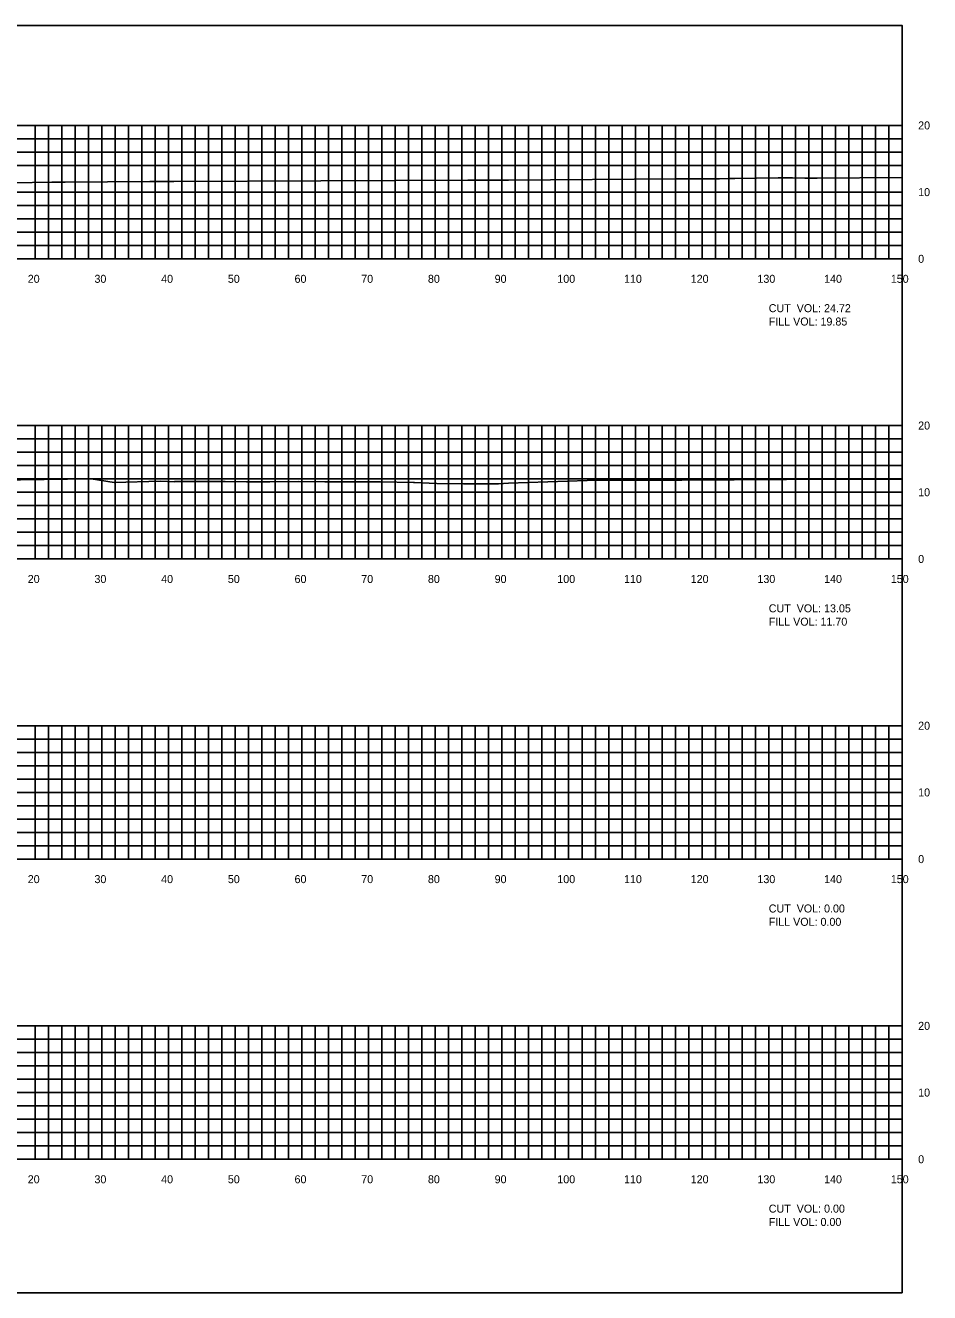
# Model space of a CAD drawing. Extents: x 1800768 to 1802445, y 250079 to 250269.
# Drawn here: x 1802309.5 to 1802445.1, y 250079.4 to 250269.4 of the extents above; entities that cross this region are included whole.
import ezdxf

# ---------------------------------------------------------------- set-up
doc = ezdxf.new("R2010")
doc.units = 0
for name, color, linetype in [('10', 7, 'Continuous'), ('31', 7, 'Continuous'), ('60', 7, 'Continuous'), ('ANNO-TXT', 7, 'Continuous'), ('Level 62', 7, 'Continuous'), ('M-ROADS', 7, 'Continuous')]:
    doc.layers.add(name, color=color, linetype=linetype)

msp = doc.modelspace()

# ---------------------------------------------------------------- linework, layer by layer
msp.add_lwpolyline([(1802141, 250079.43), (1802441, 250079.43), (1802441, 250269.43), (1802141, 250269.43)], close=True)
at = {"layer": '60'}
for p, q in [((1802441, 250234.43), (1802441, 250254.43)), ((1802441.06, 250254.43), (1802441, 250254.43)), ((1802441.06, 250244.43), (1802441, 250244.43)), ((1802141, 250234.43), (1802441, 250234.43)), ((1802311, 250234.37), (1802311, 250234.43)), ((1802321, 250234.37), (1802321, 250234.43)), ((1802331, 250234.37), (1802331, 250234.43)), ((1802341, 250234.37), (1802341, 250234.43)), ((1802351, 250234.37), (1802351, 250234.43)), ((1802361, 250234.37), (1802361, 250234.43)), ((1802371, 250234.37), (1802371, 250234.43)), ((1802381, 250234.37), (1802381, 250234.43)), ((1802391, 250234.37), (1802391, 250234.43)), ((1802401, 250234.37), (1802401, 250234.43)), ((1802411, 250234.37), (1802411, 250234.43)), ((1802421, 250234.37), (1802421, 250234.43)), ((1802431, 250234.37), (1802431, 250234.43)), ((1802441, 250234.37), (1802441, 250234.43)), ((1802441.06, 250234.43), (1802441, 250234.43)), ((1802441, 250189.43), (1802441, 250209.43)), ((1802441.06, 250209.43), (1802441, 250209.43)), ((1802441.06, 250199.43), (1802441, 250199.43)), ((1802141, 250189.43), (1802441, 250189.43)), ((1802311, 250189.37), (1802311, 250189.43)), ((1802321, 250189.37), (1802321, 250189.43)), ((1802331, 250189.37), (1802331, 250189.43)), ((1802341, 250189.37), (1802341, 250189.43)), ((1802351, 250189.37), (1802351, 250189.43)), ((1802361, 250189.37), (1802361, 250189.43)), ((1802371, 250189.37), (1802371, 250189.43)), ((1802381, 250189.37), (1802381, 250189.43)), ((1802391, 250189.37), (1802391, 250189.43)), ((1802401, 250189.37), (1802401, 250189.43)), ((1802411, 250189.37), (1802411, 250189.43)), ((1802421, 250189.37), (1802421, 250189.43)), ((1802431, 250189.37), (1802431, 250189.43)), ((1802441, 250189.37), (1802441, 250189.43)), ((1802441.06, 250189.43), (1802441, 250189.43)), ((1802441, 250144.43), (1802441, 250164.43)), ((1802441.06, 250164.43), (1802441, 250164.43)), ((1802441.06, 250154.43), (1802441, 250154.43)), ((1802141, 250144.43), (1802441, 250144.43)), ((1802311, 250144.37), (1802311, 250144.43)), ((1802321, 250144.37), (1802321, 250144.43)), ((1802331, 250144.37), (1802331, 250144.43)), ((1802341, 250144.37), (1802341, 250144.43)), ((1802351, 250144.37), (1802351, 250144.43)), ((1802361, 250144.37), (1802361, 250144.43)), ((1802371, 250144.37), (1802371, 250144.43)), ((1802381, 250144.37), (1802381, 250144.43)), ((1802391, 250144.37), (1802391, 250144.43)), ((1802401, 250144.37), (1802401, 250144.43)), ((1802411, 250144.37), (1802411, 250144.43)), ((1802421, 250144.37), (1802421, 250144.43)), ((1802431, 250144.37), (1802431, 250144.43)), ((1802441, 250144.37), (1802441, 250144.43)), ((1802441.06, 250144.43), (1802441, 250144.43)), ((1802441, 250099.43), (1802441, 250119.43)), ((1802441.06, 250119.43), (1802441, 250119.43)), ((1802441.06, 250109.43), (1802441, 250109.43)), ((1802141, 250099.43), (1802441, 250099.43)), ((1802311, 250099.37), (1802311, 250099.43)), ((1802321, 250099.37), (1802321, 250099.43)), ((1802331, 250099.37), (1802331, 250099.43)), ((1802341, 250099.37), (1802341, 250099.43)), ((1802351, 250099.37), (1802351, 250099.43)), ((1802361, 250099.37), (1802361, 250099.43)), ((1802371, 250099.37), (1802371, 250099.43)), ((1802381, 250099.37), (1802381, 250099.43)), ((1802391, 250099.37), (1802391, 250099.43)), ((1802401, 250099.37), (1802401, 250099.43)), ((1802411, 250099.37), (1802411, 250099.43)), ((1802421, 250099.37), (1802421, 250099.43)), ((1802431, 250099.37), (1802431, 250099.43)), ((1802441, 250099.37), (1802441, 250099.43)), ((1802441.06, 250099.43), (1802441, 250099.43))]:
    msp.add_line(p, q, dxfattribs=at)
at = {"layer": 'Level 62'}
for p, q in [((1802141, 250254.43), (1802441, 250254.43)), ((1802311, 250234.43), (1802311, 250254.43)), ((1802313, 250234.43), (1802313, 250254.43)), ((1802315, 250234.43), (1802315, 250254.43)), ((1802317, 250234.43), (1802317, 250254.43)), ((1802319, 250234.43), (1802319, 250254.43)), ((1802321, 250234.43), (1802321, 250254.43)), ((1802323, 250234.43), (1802323, 250254.43)), ((1802325, 250234.43), (1802325, 250254.43)), ((1802327, 250234.43), (1802327, 250254.43)), ((1802329, 250234.43), (1802329, 250254.43)), ((1802331, 250234.43), (1802331, 250254.43)), ((1802333, 250234.43), (1802333, 250254.43)), ((1802335, 250234.43), (1802335, 250254.43)), ((1802337, 250234.43), (1802337, 250254.43)), ((1802339, 250234.43), (1802339, 250254.43)), ((1802341, 250234.43), (1802341, 250254.43)), ((1802343, 250234.43), (1802343, 250254.43)), ((1802345, 250234.43), (1802345, 250254.43)), ((1802347, 250234.43), (1802347, 250254.43)), ((1802349, 250234.43), (1802349, 250254.43)), ((1802351, 250234.43), (1802351, 250254.43)), ((1802353, 250234.43), (1802353, 250254.43)), ((1802355, 250234.43), (1802355, 250254.43)), ((1802357, 250234.43), (1802357, 250254.43)), ((1802359, 250234.43), (1802359, 250254.43)), ((1802361, 250234.43), (1802361, 250254.43)), ((1802363, 250234.43), (1802363, 250254.43)), ((1802365, 250234.43), (1802365, 250254.43)), ((1802367, 250234.43), (1802367, 250254.43)), ((1802369, 250234.43), (1802369, 250254.43)), ((1802371, 250234.43), (1802371, 250254.43)), ((1802373, 250234.43), (1802373, 250254.43)), ((1802375, 250234.43), (1802375, 250254.43)), ((1802377, 250234.43), (1802377, 250254.43)), ((1802379, 250234.43), (1802379, 250254.43)), ((1802381, 250234.43), (1802381, 250254.43)), ((1802383, 250234.43), (1802383, 250254.43)), ((1802385, 250234.43), (1802385, 250254.43)), ((1802387, 250234.43), (1802387, 250254.43)), ((1802389, 250234.43), (1802389, 250254.43)), ((1802391, 250234.43), (1802391, 250254.43)), ((1802393, 250234.43), (1802393, 250254.43)), ((1802395, 250234.43), (1802395, 250254.43)), ((1802397, 250234.43), (1802397, 250254.43)), ((1802399, 250234.43), (1802399, 250254.43)), ((1802401, 250234.43), (1802401, 250254.43)), ((1802403, 250234.43), (1802403, 250254.43)), ((1802405, 250234.43), (1802405, 250254.43)), ((1802407, 250234.43), (1802407, 250254.43)), ((1802409, 250234.43), (1802409, 250254.43)), ((1802411, 250234.43), (1802411, 250254.43)), ((1802413, 250234.43), (1802413, 250254.43)), ((1802415, 250234.43), (1802415, 250254.43)), ((1802417, 250234.43), (1802417, 250254.43)), ((1802419, 250234.43), (1802419, 250254.43)), ((1802421, 250234.43), (1802421, 250254.43)), ((1802423, 250234.43), (1802423, 250254.43)), ((1802425, 250234.43), (1802425, 250254.43)), ((1802427, 250234.43), (1802427, 250254.43)), ((1802429, 250234.43), (1802429, 250254.43)), ((1802431, 250234.43), (1802431, 250254.43)), ((1802433, 250234.43), (1802433, 250254.43)), ((1802435, 250234.43), (1802435, 250254.43)), ((1802437, 250234.43), (1802437, 250254.43)), ((1802439, 250234.43), (1802439, 250254.43)), ((1802441, 250234.43), (1802441, 250254.43)), ((1802141, 250252.43), (1802441, 250252.43)), ((1802141, 250250.43), (1802441, 250250.43)), ((1802141, 250248.43), (1802441, 250248.43)), ((1802141, 250244.43), (1802441, 250244.43)), ((1802141, 250242.43), (1802441, 250242.43)), ((1802141, 250240.43), (1802441, 250240.43)), ((1802141, 250238.43), (1802441, 250238.43)), ((1802141, 250236.43), (1802441, 250236.43)), ((1802141, 250234.43), (1802441, 250234.43)), ((1802141, 250209.43), (1802441, 250209.43)), ((1802311, 250189.43), (1802311, 250209.43)), ((1802313, 250189.43), (1802313, 250209.43)), ((1802315, 250189.43), (1802315, 250209.43)), ((1802317, 250189.43), (1802317, 250209.43)), ((1802319, 250189.43), (1802319, 250209.43)), ((1802321, 250189.43), (1802321, 250209.43)), ((1802323, 250189.43), (1802323, 250209.43)), ((1802325, 250189.43), (1802325, 250209.43)), ((1802327, 250189.43), (1802327, 250209.43)), ((1802329, 250189.43), (1802329, 250209.43)), ((1802331, 250189.43), (1802331, 250209.43)), ((1802333, 250189.43), (1802333, 250209.43)), ((1802335, 250189.43), (1802335, 250209.43)), ((1802337, 250189.43), (1802337, 250209.43)), ((1802339, 250189.43), (1802339, 250209.43)), ((1802341, 250189.43), (1802341, 250209.43)), ((1802343, 250189.43), (1802343, 250209.43)), ((1802345, 250189.43), (1802345, 250209.43)), ((1802347, 250189.43), (1802347, 250209.43)), ((1802349, 250189.43), (1802349, 250209.43)), ((1802351, 250189.43), (1802351, 250209.43)), ((1802353, 250189.43), (1802353, 250209.43)), ((1802355, 250189.43), (1802355, 250209.43)), ((1802357, 250189.43), (1802357, 250209.43)), ((1802359, 250189.43), (1802359, 250209.43)), ((1802361, 250189.43), (1802361, 250209.43)), ((1802363, 250189.43), (1802363, 250209.43)), ((1802365, 250189.43), (1802365, 250209.43)), ((1802367, 250189.43), (1802367, 250209.43)), ((1802369, 250189.43), (1802369, 250209.43)), ((1802371, 250189.43), (1802371, 250209.43)), ((1802373, 250189.43), (1802373, 250209.43)), ((1802375, 250189.43), (1802375, 250209.43)), ((1802377, 250189.43), (1802377, 250209.43)), ((1802379, 250189.43), (1802379, 250209.43)), ((1802381, 250189.43), (1802381, 250209.43)), ((1802383, 250189.43), (1802383, 250209.43)), ((1802385, 250189.43), (1802385, 250209.43)), ((1802387, 250189.43), (1802387, 250209.43)), ((1802389, 250189.43), (1802389, 250209.43)), ((1802391, 250189.43), (1802391, 250209.43)), ((1802393, 250189.43), (1802393, 250209.43)), ((1802395, 250189.43), (1802395, 250209.43)), ((1802397, 250189.43), (1802397, 250209.43)), ((1802399, 250189.43), (1802399, 250209.43)), ((1802401, 250189.43), (1802401, 250209.43)), ((1802403, 250189.43), (1802403, 250209.43)), ((1802405, 250189.43), (1802405, 250209.43)), ((1802407, 250189.43), (1802407, 250209.43)), ((1802409, 250189.43), (1802409, 250209.43)), ((1802411, 250189.43), (1802411, 250209.43)), ((1802413, 250189.43), (1802413, 250209.43)), ((1802415, 250189.43), (1802415, 250209.43)), ((1802417, 250189.43), (1802417, 250209.43)), ((1802419, 250189.43), (1802419, 250209.43)), ((1802421, 250189.43), (1802421, 250209.43)), ((1802423, 250189.43), (1802423, 250209.43)), ((1802425, 250189.43), (1802425, 250209.43)), ((1802427, 250189.43), (1802427, 250209.43)), ((1802429, 250189.43), (1802429, 250209.43)), ((1802431, 250189.43), (1802431, 250209.43)), ((1802433, 250189.43), (1802433, 250209.43)), ((1802435, 250189.43), (1802435, 250209.43)), ((1802437, 250189.43), (1802437, 250209.43)), ((1802439, 250189.43), (1802439, 250209.43)), ((1802441, 250189.43), (1802441, 250209.43)), ((1802141, 250207.43), (1802441, 250207.43)), ((1802141, 250205.43), (1802441, 250205.43)), ((1802141, 250203.43), (1802441, 250203.43)), ((1802141, 250201.43), (1802441, 250201.43)), ((1802141, 250199.43), (1802441, 250199.43)), ((1802141, 250197.43), (1802441, 250197.43)), ((1802141, 250195.43), (1802441, 250195.43)), ((1802141, 250193.43), (1802441, 250193.43)), ((1802141, 250191.43), (1802441, 250191.43)), ((1802141, 250189.43), (1802441, 250189.43)), ((1802141, 250164.43), (1802441, 250164.43)), ((1802311, 250144.43), (1802311, 250164.43)), ((1802313, 250144.43), (1802313, 250164.43)), ((1802315, 250144.43), (1802315, 250164.43)), ((1802317, 250144.43), (1802317, 250164.43)), ((1802319, 250144.43), (1802319, 250164.43)), ((1802321, 250144.43), (1802321, 250164.43)), ((1802323, 250144.43), (1802323, 250164.43)), ((1802325, 250144.43), (1802325, 250164.43)), ((1802327, 250144.43), (1802327, 250164.43)), ((1802329, 250144.43), (1802329, 250164.43)), ((1802331, 250144.43), (1802331, 250164.43)), ((1802333, 250144.43), (1802333, 250164.43)), ((1802335, 250144.43), (1802335, 250164.43)), ((1802337, 250144.43), (1802337, 250164.43)), ((1802339, 250144.43), (1802339, 250164.43)), ((1802341, 250144.43), (1802341, 250164.43)), ((1802343, 250144.43), (1802343, 250164.43)), ((1802345, 250144.43), (1802345, 250164.43)), ((1802347, 250144.43), (1802347, 250164.43)), ((1802349, 250144.43), (1802349, 250164.43)), ((1802351, 250144.43), (1802351, 250164.43)), ((1802353, 250144.43), (1802353, 250164.43)), ((1802355, 250144.43), (1802355, 250164.43)), ((1802357, 250144.43), (1802357, 250164.43)), ((1802359, 250144.43), (1802359, 250164.43)), ((1802361, 250144.43), (1802361, 250164.43)), ((1802363, 250144.43), (1802363, 250164.43)), ((1802365, 250144.43), (1802365, 250164.43)), ((1802367, 250144.43), (1802367, 250164.43)), ((1802369, 250144.43), (1802369, 250164.43)), ((1802371, 250144.43), (1802371, 250164.43)), ((1802373, 250144.43), (1802373, 250164.43)), ((1802375, 250144.43), (1802375, 250164.43)), ((1802377, 250144.43), (1802377, 250164.43)), ((1802379, 250144.43), (1802379, 250164.43)), ((1802381, 250144.43), (1802381, 250164.43)), ((1802383, 250144.43), (1802383, 250164.43)), ((1802385, 250144.43), (1802385, 250164.43)), ((1802387, 250144.43), (1802387, 250164.43)), ((1802389, 250144.43), (1802389, 250164.43)), ((1802391, 250144.43), (1802391, 250164.43)), ((1802393, 250144.43), (1802393, 250164.43)), ((1802395, 250144.43), (1802395, 250164.43)), ((1802397, 250144.43), (1802397, 250164.43)), ((1802399, 250144.43), (1802399, 250164.43)), ((1802401, 250144.43), (1802401, 250164.43)), ((1802403, 250144.43), (1802403, 250164.43)), ((1802405, 250144.43), (1802405, 250164.43)), ((1802407, 250144.43), (1802407, 250164.43)), ((1802409, 250144.43), (1802409, 250164.43)), ((1802411, 250144.43), (1802411, 250164.43)), ((1802413, 250144.43), (1802413, 250164.43)), ((1802415, 250144.43), (1802415, 250164.43)), ((1802417, 250144.43), (1802417, 250164.43)), ((1802419, 250144.43), (1802419, 250164.43)), ((1802421, 250144.43), (1802421, 250164.43)), ((1802423, 250144.43), (1802423, 250164.43)), ((1802425, 250144.43), (1802425, 250164.43)), ((1802427, 250144.43), (1802427, 250164.43)), ((1802429, 250144.43), (1802429, 250164.43)), ((1802431, 250144.43), (1802431, 250164.43)), ((1802433, 250144.43), (1802433, 250164.43)), ((1802435, 250144.43), (1802435, 250164.43)), ((1802437, 250144.43), (1802437, 250164.43)), ((1802439, 250144.43), (1802439, 250164.43)), ((1802441, 250144.43), (1802441, 250164.43)), ((1802141, 250162.43), (1802441, 250162.43)), ((1802141, 250160.43), (1802441, 250160.43)), ((1802141, 250158.43), (1802441, 250158.43)), ((1802141, 250156.43), (1802441, 250156.43)), ((1802141, 250154.43), (1802441, 250154.43)), ((1802141, 250152.43), (1802441, 250152.43)), ((1802141, 250150.43), (1802441, 250150.43)), ((1802141, 250148.43), (1802441, 250148.43)), ((1802141, 250146.43), (1802441, 250146.43)), ((1802141, 250144.43), (1802441, 250144.43)), ((1802141, 250119.43), (1802441, 250119.43)), ((1802311, 250099.43), (1802311, 250119.43)), ((1802313, 250099.43), (1802313, 250119.43)), ((1802315, 250099.43), (1802315, 250119.43)), ((1802317, 250099.43), (1802317, 250119.43)), ((1802319, 250099.43), (1802319, 250119.43)), ((1802321, 250099.43), (1802321, 250119.43)), ((1802323, 250099.43), (1802323, 250119.43)), ((1802325, 250099.43), (1802325, 250119.43)), ((1802327, 250099.43), (1802327, 250119.43)), ((1802329, 250099.43), (1802329, 250119.43)), ((1802331, 250099.43), (1802331, 250119.43)), ((1802333, 250099.43), (1802333, 250119.43)), ((1802335, 250099.43), (1802335, 250119.43)), ((1802337, 250099.43), (1802337, 250119.43)), ((1802339, 250099.43), (1802339, 250119.43)), ((1802341, 250099.43), (1802341, 250119.43)), ((1802343, 250099.43), (1802343, 250119.43)), ((1802345, 250099.43), (1802345, 250119.43)), ((1802347, 250099.43), (1802347, 250119.43)), ((1802349, 250099.43), (1802349, 250119.43)), ((1802351, 250099.43), (1802351, 250119.43)), ((1802353, 250099.43), (1802353, 250119.43)), ((1802355, 250099.43), (1802355, 250119.43)), ((1802357, 250099.43), (1802357, 250119.43)), ((1802359, 250099.43), (1802359, 250119.43)), ((1802361, 250099.43), (1802361, 250119.43)), ((1802363, 250099.43), (1802363, 250119.43)), ((1802365, 250099.43), (1802365, 250119.43)), ((1802367, 250099.43), (1802367, 250119.43)), ((1802369, 250099.43), (1802369, 250119.43)), ((1802371, 250099.43), (1802371, 250119.43)), ((1802373, 250099.43), (1802373, 250119.43)), ((1802375, 250099.43), (1802375, 250119.43)), ((1802377, 250099.43), (1802377, 250119.43)), ((1802379, 250099.43), (1802379, 250119.43)), ((1802381, 250099.43), (1802381, 250119.43)), ((1802383, 250099.43), (1802383, 250119.43)), ((1802385, 250099.43), (1802385, 250119.43)), ((1802387, 250099.43), (1802387, 250119.43)), ((1802389, 250099.43), (1802389, 250119.43)), ((1802391, 250099.43), (1802391, 250119.43)), ((1802393, 250099.43), (1802393, 250119.43)), ((1802395, 250099.43), (1802395, 250119.43)), ((1802397, 250099.43), (1802397, 250119.43)), ((1802399, 250099.43), (1802399, 250119.43)), ((1802401, 250099.43), (1802401, 250119.43)), ((1802403, 250099.43), (1802403, 250119.43)), ((1802405, 250099.43), (1802405, 250119.43)), ((1802407, 250099.43), (1802407, 250119.43)), ((1802409, 250099.43), (1802409, 250119.43)), ((1802411, 250099.43), (1802411, 250119.43)), ((1802413, 250099.43), (1802413, 250119.43)), ((1802415, 250099.43), (1802415, 250119.43)), ((1802417, 250099.43), (1802417, 250119.43)), ((1802419, 250099.43), (1802419, 250119.43)), ((1802421, 250099.43), (1802421, 250119.43)), ((1802423, 250099.43), (1802423, 250119.43)), ((1802425, 250099.43), (1802425, 250119.43)), ((1802427, 250099.43), (1802427, 250119.43)), ((1802429, 250099.43), (1802429, 250119.43)), ((1802431, 250099.43), (1802431, 250119.43)), ((1802433, 250099.43), (1802433, 250119.43)), ((1802435, 250099.43), (1802435, 250119.43)), ((1802437, 250099.43), (1802437, 250119.43)), ((1802439, 250099.43), (1802439, 250119.43)), ((1802441, 250099.43), (1802441, 250119.43)), ((1802141, 250117.43), (1802441, 250117.43)), ((1802141, 250115.43), (1802441, 250115.43)), ((1802141, 250113.43), (1802441, 250113.43)), ((1802141, 250111.43), (1802441, 250111.43)), ((1802141, 250109.43), (1802441, 250109.43)), ((1802141, 250107.43), (1802441, 250107.43)), ((1802141, 250105.43), (1802441, 250105.43)), ((1802141, 250103.43), (1802441, 250103.43)), ((1802141, 250101.43), (1802441, 250101.43)), ((1802141, 250099.43), (1802441, 250099.43))]:
    msp.add_line(p, q, dxfattribs=at)
at = {"layer": 'M-ROADS'}
for points in [[(1802301.78, 250245.74), (1802313.5, 250245.93), (1802313.6, 250245.93), (1802314.06, 250245.93), (1802314.06, 250245.93), (1802314.13, 250245.93), (1802314.2, 250245.93), (1802314.2, 250245.93), (1802314.26, 250245.94), (1802314.33, 250245.93), (1802314.33, 250245.94), (1802314.4, 250245.94), (1802314.47, 250245.94), (1802314.6, 250245.94), (1802314.6, 250245.94), (1802314.66, 250245.94), (1802314.73, 250245.94), (1802314.73, 250245.94), (1802315.18, 250245.93), (1802315.26, 250245.93), (1802315.35, 250245.94), (1802315.35, 250245.94), (1802315.43, 250245.93), (1802315.52, 250245.93), (1802315.52, 250245.93), (1802328.19, 250246), (1802328.26, 250246), (1802328.33, 250246.01), (1802328.34, 250246.01), (1802328.41, 250246.01), (1802328.48, 250246.01), (1802328.49, 250246.01), (1802328.55, 250246.01), (1802330.47, 250246.03), (1802330.67, 250246.03), (1802330.72, 250246.03), (1802330.81, 250246.03), (1802331.16, 250246.03), (1802331.16, 250246.02), (1802331.16, 250246.02), (1802331.18, 250246.02), (1802331.74, 250246.03), (1802331.81, 250246.03), (1802375.87, 250246.22), (1802376.14, 250246.22), (1802376.45, 250246.22), (1802378.21, 250246.22), (1802378.26, 250246.23), (1802378.39, 250246.23), (1802380.85, 250246.24), (1802381.99, 250246.24), (1802407.14, 250246.41), (1802407.37, 250246.41), (1802407.58, 250246.41), (1802407.7, 250246.41), (1802408.32, 250246.42), (1802411.6, 250246.42), (1802413.61, 250246.43), (1802415.05, 250246.47), (1802415.19, 250246.47), (1802415.9, 250246.47), (1802422.39, 250246.56), (1802422.47, 250246.57), (1802422.69, 250246.57), (1802422.79, 250246.57), (1802423.06, 250246.57), (1802424.55, 250246.56), (1802426.39, 250246.54), (1802428.26, 250246.53), (1802441, 250246.6)], [(1802305.25, 250201.23), (1802319.39, 250201.44), (1802322.86, 250200.9), (1802329.79, 250201.07), (1802331.83, 250201), (1802331.89, 250201.04), (1802335.67, 250201.05), (1802338.82, 250201.02), (1802339.49, 250201.03), (1802342.7, 250201), (1802346.22, 250200.98), (1802350.48, 250201.02), (1802354.45, 250201.01), (1802358.18, 250201), (1802360.9, 250200.97), (1802362.79, 250200.97), (1802367.75, 250200.87), (1802367.91, 250200.87), (1802368.95, 250200.84), (1802371.23, 250200.72), (1802375.22, 250200.71), (1802379.35, 250200.7), (1802379.8, 250200.7), (1802380.49, 250200.7), (1802381.99, 250200.79), (1802393.76, 250201.17), (1802407.95, 250201.22), (1802423.67, 250201.33), (1802441, 250201.37)]]:
    msp.add_lwpolyline(points, dxfattribs=at)

# ---------------------------------------------------------------- texts
at = {"layer": '10'}
for s, p in [('20', (1802309.9, 250230.83)), ('30', (1802319.9, 250230.83)), ('40', (1802329.9, 250230.83)), ('50', (1802339.9, 250230.83)), ('60', (1802349.9, 250230.83)), ('70', (1802359.9, 250230.83)), ('80', (1802369.9, 250230.83)), ('90', (1802379.9, 250230.83)), ('100', (1802389.3, 250230.83)), ('110', (1802399.3, 250230.83)), ('120', (1802409.3, 250230.83)), ('130', (1802419.3, 250230.83)), ('140', (1802429.3, 250230.83)), ('150', (1802439.3, 250230.83)), ('20', (1802309.9, 250185.83)), ('30', (1802319.9, 250185.83)), ('40', (1802329.9, 250185.83)), ('50', (1802339.9, 250185.83)), ('60', (1802349.9, 250185.83)), ('70', (1802359.9, 250185.83)), ('80', (1802369.9, 250185.83)), ('90', (1802379.9, 250185.83)), ('100', (1802389.3, 250185.83)), ('110', (1802399.3, 250185.83)), ('120', (1802409.3, 250185.83)), ('130', (1802419.3, 250185.83)), ('140', (1802429.3, 250185.83)), ('150', (1802439.3, 250185.83)), ('20', (1802309.9, 250140.83)), ('30', (1802319.9, 250140.83)), ('40', (1802329.9, 250140.83)), ('50', (1802339.9, 250140.83)), ('60', (1802349.9, 250140.83)), ('70', (1802359.9, 250140.83)), ('80', (1802369.9, 250140.83)), ('90', (1802379.9, 250140.83)), ('100', (1802389.3, 250140.83)), ('110', (1802399.3, 250140.83)), ('120', (1802409.3, 250140.83)), ('130', (1802419.3, 250140.83)), ('140', (1802429.3, 250140.83)), ('150', (1802439.3, 250140.83)), ('20', (1802309.9, 250095.83)), ('30', (1802319.9, 250095.83)), ('40', (1802329.9, 250095.83)), ('50', (1802339.9, 250095.83)), ('60', (1802349.9, 250095.83)), ('70', (1802359.9, 250095.83)), ('80', (1802369.9, 250095.83)), ('90', (1802379.9, 250095.83)), ('100', (1802389.3, 250095.83)), ('110', (1802399.3, 250095.83)), ('120', (1802409.3, 250095.83)), ('130', (1802419.3, 250095.83)), ('140', (1802429.3, 250095.83)), ('150', (1802439.3, 250095.83))]:
    msp.add_text(s, height=1.2, dxfattribs=at).set_placement(p)
at = {"layer": '31'}
for s, p in [('20', (1802443.4, 250253.83)), ('10', (1802443.4, 250243.83)), ('0', (1802443.4, 250233.83)), ('20', (1802443.4, 250208.83)), ('10', (1802443.4, 250198.83)), ('0', (1802443.4, 250188.83)), ('20', (1802443.4, 250163.83)), ('10', (1802443.4, 250153.83)), ('0', (1802443.4, 250143.83)), ('20', (1802443.4, 250118.83)), ('10', (1802443.4, 250108.83)), ('0', (1802443.4, 250098.83))]:
    msp.add_text(s, height=1.2, dxfattribs=at).set_placement(p)
at = {"layer": 'ANNO-TXT'}
for s, p in [('CUT  VOL: 24.72', (1802421, 250226.43)), ('FILL VOL: 19.85', (1802421, 250224.43)), ('CUT  VOL: 13.05', (1802421, 250181.43)), ('FILL VOL: 11.70', (1802421, 250179.43)), ('CUT  VOL: 0.00', (1802421, 250136.43)), ('FILL VOL: 0.00', (1802421, 250134.43)), ('CUT  VOL: 0.00', (1802421, 250091.43)), ('FILL VOL: 0.00', (1802421, 250089.43))]:
    msp.add_text(s, height=1.2, dxfattribs=at).set_placement(p)

doc.saveas('drawing.dxf')
